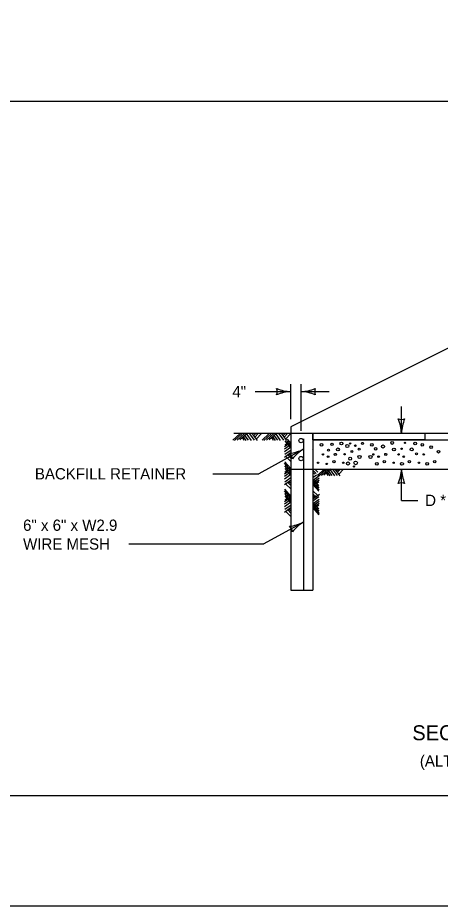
# Model space of a CAD drawing. Extents: x 49991.4 to 50021, y 49987.6 to 50011.4.
# Drawn here: x 50007.022 to 50009.276, y 49987.799 to 49992.532 of the extents above; entities that cross this region are included whole.
import ezdxf

# ---------------------------------------------------------------- set-up
doc = ezdxf.new("R2010")
doc.units = 0
for name, color, linetype in [('Level 1', 7, 'Continuous'), ('Level 2', 7, 'Continuous'), ('Level 3', 7, 'Continuous')]:
    doc.layers.add(name, color=color, linetype=linetype)

msp = doc.modelspace()

# ---------------------------------------------------------------- linework, layer by layer
at = {"layer": 'Level 1'}
for p, q in [((50010.2587, 49991.2434), (50008.4789, 49990.3535)), ((50008.4789, 49990.3535), (50008.4789, 49989.4831)), ((50008.2055, 49990.3145), (50008.1685, 49990.2823)), ((50008.1748, 49990.3188), (50008.5959, 49990.3188)), ((50008.2164, 49990.3145), (50008.1775, 49990.2806)), ((50008.2302, 49990.3147), (50008.1922, 49990.2816)), ((50008.2434, 49990.3149), (50008.2071, 49990.2833)), ((50008.2199, 49990.2939), (50008.2284, 49990.2822)), ((50008.2261, 49990.2978), (50008.2386, 49990.2806)), ((50008.2339, 49990.305), (50008.2512, 49990.2812)), ((50008.2435, 49990.3115), (50008.2661, 49990.2806)), ((50008.2582, 49990.3153), (50008.2827, 49990.2816)), ((50008.2725, 49990.3155), (50008.2985, 49990.2798)), ((50008.2795, 49990.304), (50008.2903, 49990.3155)), ((50008.286, 49990.2972), (50008.3043, 49990.3165)), ((50008.2955, 49990.2881), (50008.3209, 49990.3151)), ((50008.3619, 49990.3145), (50008.3248, 49990.2823)), ((50008.3728, 49990.3145), (50008.3339, 49990.2806)), ((50008.3866, 49990.3147), (50008.3485, 49990.2816)), ((50008.3998, 49990.3149), (50008.3633, 49990.2833)), ((50008.3763, 49990.2939), (50008.3848, 49990.2822)), ((50008.3825, 49990.2978), (50008.395, 49990.2806)), ((50008.3902, 49990.305), (50008.4076, 49990.2812)), ((50008.3998, 49990.3115), (50008.4223, 49990.2806)), ((50008.4144, 49990.3153), (50008.439, 49990.2816)), ((50008.4287, 49990.3155), (50008.4549, 49990.2798)), ((50008.4358, 49990.304), (50008.4466, 49990.3155)), ((50008.4423, 49990.2972), (50008.4605, 49990.3165)), ((50008.4519, 49990.2881), (50008.4773, 49990.3151)), ((50008.4789, 49990.2662), (50008.4607, 49990.2871)), ((50008.4789, 49990.3145), (50008.4789, 49990.3145)), ((50008.5457, 49990.2888), (50008.5457, 49989.4831)), ((50008.5959, 49990.3188), (50010.5584, 49990.3188)), ((50008.5959, 49990.3188), (50009.194, 49990.3188)), ((50008.5959, 49990.2833), (50008.5959, 49990.3188)), ((50008.5959, 49990.3145), (50008.5959, 49989.4831)), ((50008.5959, 49990.2833), (50010.5584, 49990.2833)), ((50009.194, 49990.2833), (50008.5959, 49990.2833)), ((50009.194, 49990.3188), (50009.194, 49990.2833)), ((50008.4621, 49990.2588), (50008.445, 49990.2462)), ((50008.4759, 49990.2428), (50008.445, 49990.2203)), ((50008.4693, 49990.2516), (50008.4455, 49990.2343)), ((50008.4582, 49990.2644), (50008.4466, 49990.2559)), ((50008.4793, 49990.241), (50008.4477, 49990.2774)), ((50008.4791, 49990.2534), (50008.4586, 49990.2769)), ((50008.5959, 49990.279), (50008.5959, 49990.279)), ((50008.4799, 49990.2157), (50008.4442, 49990.1897)), ((50008.4796, 49990.2291), (50008.446, 49990.2045)), ((50008.4525, 49990.1941), (50008.4793, 49990.1687)), ((50008.4616, 49990.2029), (50008.4809, 49990.1845)), ((50008.4684, 49990.2086), (50008.4798, 49990.1978)), ((50008.4789, 49990.1197), (50008.445, 49990.1586)), ((50008.4791, 49990.1067), (50008.446, 49990.1448)), ((50008.4789, 49990.13), (50008.4466, 49990.167)), ((50008.4621, 49990.1123), (50008.445, 49990.0997)), ((50008.4759, 49990.0962), (50008.445, 49990.0736)), ((50008.4693, 49990.1051), (50008.4455, 49990.0878)), ((50008.4582, 49990.1179), (50008.4466, 49990.1094)), ((50008.4793, 49990.0945), (50008.4477, 49990.1309)), ((50008.4789, 49990.1273), (50010.5584, 49990.1273)), ((50008.6131, 49990.1049), (50008.5959, 49990.1212)), ((50008.6063, 49990.1005), (50008.5959, 49990.1104)), ((50008.5959, 49990.0826), (50008.6148, 49990.0964)), ((50008.6223, 49990.1119), (50008.606, 49990.1273)), ((50008.6579, 49990.1262), (50008.6209, 49990.0939)), ((50008.6677, 49990.1262), (50008.6288, 49990.0922)), ((50008.68, 49990.1263), (50008.6419, 49990.0932)), ((50008.6916, 49990.1266), (50008.6552, 49990.0948)), ((50008.6682, 49990.1055), (50008.6767, 49990.0939)), ((50008.6736, 49990.1094), (50008.6861, 49990.0922)), ((50008.6802, 49990.1166), (50008.6975, 49990.0928)), ((50008.6885, 49990.1232), (50008.711, 49990.0923)), ((50008.7014, 49990.1269), (50008.7259, 49990.0933)), ((50008.714, 49990.1271), (50008.7401, 49990.0915)), ((50008.7211, 49990.1157), (50008.7319, 49990.1271)), ((50008.7265, 49990.1088), (50008.744, 49990.1273)), ((50008.7346, 49990.0996), (50008.7601, 49990.1266)), ((50008.4799, 49990.0692), (50008.4442, 49990.0431)), ((50008.4796, 49990.0825), (50008.446, 49990.058)), ((50008.4525, 49990.0476), (50008.4793, 49990.0221)), ((50008.4616, 49990.0562), (50008.4809, 49990.038)), ((50008.4684, 49990.0621), (50008.4798, 49990.0513)), ((50008.5959, 49990.0758), (50008.6271, 49990.04)), ((50008.5959, 49990.0658), (50008.6287, 49990.028)), ((50008.5959, 49990.055), (50008.6297, 49990.0163)), ((50008.5959, 49990.0461), (50008.6281, 49990.0092)), ((50008.5989, 49990.0706), (50008.6297, 49990.0931)), ((50008.6055, 49990.0634), (50008.6292, 49990.0807)), ((50008.6127, 49990.0577), (50008.6297, 49990.0701)), ((50008.6165, 49990.0531), (50008.6281, 49990.0616)), ((50008.4789, 49989.9732), (50008.445, 49990.0121)), ((50008.4789, 49989.9835), (50008.4466, 49990.0205)), ((50008.6223, 49989.9869), (50008.5959, 49990.0118)), ((50008.4621, 49989.9656), (50008.445, 49989.9531)), ((50008.4693, 49989.9585), (50008.4455, 49989.9411)), ((50008.4791, 49989.9602), (50008.446, 49989.9983)), ((50008.4582, 49989.9714), (50008.4466, 49989.9629)), ((50008.4793, 49989.948), (50008.4477, 49989.9843)), ((50008.6131, 49989.98), (50008.5959, 49989.9963)), ((50008.5959, 49989.9692), (50008.6305, 49989.9944)), ((50008.6063, 49989.9756), (50008.5959, 49989.9855)), ((50008.5959, 49989.9577), (50008.6287, 49989.9817)), ((50008.5989, 49989.9456), (50008.6297, 49989.9681)), ((50008.6055, 49989.9384), (50008.6292, 49989.9558)), ((50008.4799, 49989.9227), (50008.4442, 49989.8966)), ((50008.4759, 49989.9497), (50008.445, 49989.9271)), ((50008.4796, 49989.936), (50008.446, 49989.9115)), ((50008.4616, 49989.9097), (50008.4809, 49989.8915)), ((50008.4684, 49989.9156), (50008.4798, 49989.9048)), ((50008.5959, 49989.9509), (50008.6271, 49989.915)), ((50008.5959, 49989.9407), (50008.6287, 49989.903)), ((50008.5959, 49989.9301), (50008.6297, 49989.8912)), ((50008.5959, 49989.9212), (50008.6281, 49989.8841)), ((50008.6127, 49989.9327), (50008.6297, 49989.9452)), ((50008.6165, 49989.9282), (50008.6281, 49989.9367)), ((50008.4525, 49989.9011), (50008.4793, 49989.8755)), ((50008.4789, 49989.7217), (50008.4789, 49989.7217)), ((50008.4789, 49989.4831), (50008.5959, 49989.4831))]:
    msp.add_line(p, q, dxfattribs=at)
for points in [[(49999.3835, 49998.9992), (50016.7501, 49998.9992), (50016.7501, 49987.7988), (49999.3835, 49987.7988)], [(49999.5517, 49992.0867), (50014.5753, 49992.0867), (50014.5753, 49988.387), (49999.5517, 49988.387)]]:
    msp.add_lwpolyline(points, close=True, dxfattribs=at)
for centre, radius in [((50008.5333, 49990.2792), 0.0116), ((50008.6422, 49990.2567), 0.00684), ((50008.6981, 49990.2596), 0.00552), ((50008.7299, 49990.2326), 0.00765), ((50008.7483, 49990.2637), 0.00765), ((50008.7798, 49990.2507), 0.00824), ((50008.7951, 49990.2645), 0.00341), ((50008.8226, 49990.2523), 0.0046), ((50008.8426, 49990.2334), 0.00552), ((50008.8609, 49990.2645), 0.00552), ((50008.9111, 49990.2567), 0.00684), ((50008.9308, 49990.2355), 0.00684), ((50008.9704, 49990.2479), 0.00824), ((50009.0188, 49990.267), 0.00765), ((50009.0287, 49990.2317), 0.00765), ((50009.0696, 49990.2362), 0.00346), ((50009.088, 49990.2673), 0.00346), ((50009.1231, 49990.2326), 0.00765), ((50009.1415, 49990.2637), 0.00765), ((50009.1799, 49990.2567), 0.00684), ((50009.2265, 49990.244), 0.00684), ((50008.5328, 49990.1836), 0.0116), ((50008.6499, 49990.2058), 0.00341), ((50008.6774, 49990.1935), 0.0046), ((50008.6797, 49990.2286), 0.00552), ((50008.7157, 49990.2058), 0.00552), ((50008.7654, 49990.2066), 0.00341), ((50008.7951, 49990.183), 0.00766), ((50008.8043, 49990.2212), 0.0046), ((50008.8446, 49990.192), 0.00824), ((50008.9034, 49990.192), 0.00824), ((50008.9187, 49990.2058), 0.00341), ((50008.9463, 49990.1935), 0.0046), ((50008.9846, 49990.2058), 0.00552), ((50009.0532, 49990.2058), 0.00341), ((50009.0807, 49990.1935), 0.0046), ((50009.1487, 49990.2086), 0.00552), ((50009.1876, 49990.2058), 0.00341), ((50009.2663, 49990.22), 0.00684), ((50008.6238, 49990.1615), 0.00341), ((50008.6698, 49990.1548), 0.00341), ((50008.708, 49990.1676), 0.00613), ((50008.7583, 49990.1615), 0.00341), ((50008.7835, 49990.1573), 0.00824), ((50008.8158, 49990.1413), 0.00341), ((50008.8243, 49990.1605), 0.00968), ((50008.9371, 49990.1554), 0.00766), ((50008.9769, 49990.1676), 0.00613), ((50009.0271, 49990.1615), 0.00341), ((50009.0715, 49990.1554), 0.00766), ((50009.1114, 49990.1676), 0.00613), ((50009.1616, 49990.1615), 0.00341), ((50009.206, 49990.1554), 0.00766), ((50009.2458, 49990.1676), 0.00613)]:
    msp.add_circle(centre, radius, dxfattribs=at)
for centre, start in [((50008.5905, 49990.2393), 314.8637), ((50008.5905, 49990.134), 14.7763)]:
    msp.add_arc(centre, 0.00765, start, 45.1363, dxfattribs=at)
at = {"layer": 'Level 3'}
for p, q in [((50008.4789, 49990.3935), (50008.4789, 49990.5801)), ((50008.533, 49990.3308), (50008.533, 49990.5801)), ((50008.2873, 49990.5401), (50008.4789, 49990.5401)), ((50008.533, 49990.5401), (50008.683, 49990.5401)), ((50009.0686, 49990.3188), (50009.0686, 49990.4617)), ((50008.5457, 49990.2336), (50008.3075, 49990.1024)), ((50008.0627, 49990.1024), (50008.3075, 49990.1024)), ((50009.0686, 49989.9608), (50009.0686, 49990.1273)), ((50009.0686, 49989.9608), (50009.1551, 49989.9608)), ((50008.5457, 49989.845), (50008.3343, 49989.7286)), ((50007.6147, 49989.7285), (50008.3342, 49989.7285))]:
    msp.add_line(p, q, dxfattribs=at)
for centre, radius, start, end in [((50008.4881, 49990.7622), 0.2223, 247.456, 267.6395), ((50008.3507, 49990.5401), 0.0548, 342.1388, 17.8612), ((50008.4904, 49990.3073), 0.233, 92.8273, 112.0772), ((50008.5215, 49990.7728), 0.233, 272.8273, 292.0772), ((50008.5238, 49990.3179), 0.2223, 67.456, 87.6395), ((50008.6612, 49990.5401), 0.0548, 162.1388, 197.8612), ((50009.0686, 49990.447), 0.0548, 252.1388, 287.8612), ((50008.8359, 49990.3073), 0.233, 2.8273, 22.0772), ((50009.2907, 49990.3096), 0.2223, 157.456, 177.6395), ((50008.4465, 49990.4325), 0.2223, 276.3053, 296.4888), ((50008.4334, 49990.1717), 0.0548, 10.9881, 46.7105), ((50008.668, 49990.0353), 0.233, 121.6766, 140.9265), ((50008.8465, 49990.1364), 0.2223, 337.456, 357.6395), ((50009.3013, 49990.1387), 0.233, 182.8273, 202.0772), ((50009.0686, 49989.999), 0.0548, 72.1388, 107.8612), ((50008.4465, 49990.044), 0.2223, 276.3053, 296.4888), ((50008.4334, 49989.7831), 0.0548, 10.9881, 46.7105), ((50008.668, 49989.6467), 0.233, 121.6766, 140.9265)]:
    msp.add_arc(centre, radius, start, end, dxfattribs=at)

# ---------------------------------------------------------------- texts
at = {"layer": 'Level 2'}
for s, height, p in [('4"', 0.06, (50008.1666, 49990.5101)), ('BACKFILL RETAINER', 0.06, (50007.113, 49990.0724)), ('D *', 0.06, (50009.1951, 49989.9308)), ('6" x 6" x W2.9', 0.06, (50007.05, 49989.7985)), ('WIRE MESH', 0.06, (50007.05, 49989.6985)), ('SECTION B-B', 0.08, (50009.1265, 49988.6829)), ('(ALTERNATE "B")', 0.06, (50009.1668, 49988.543))]:
    msp.add_text(s, height=height, dxfattribs=at).set_placement(p)

doc.saveas('drawing.dxf')
